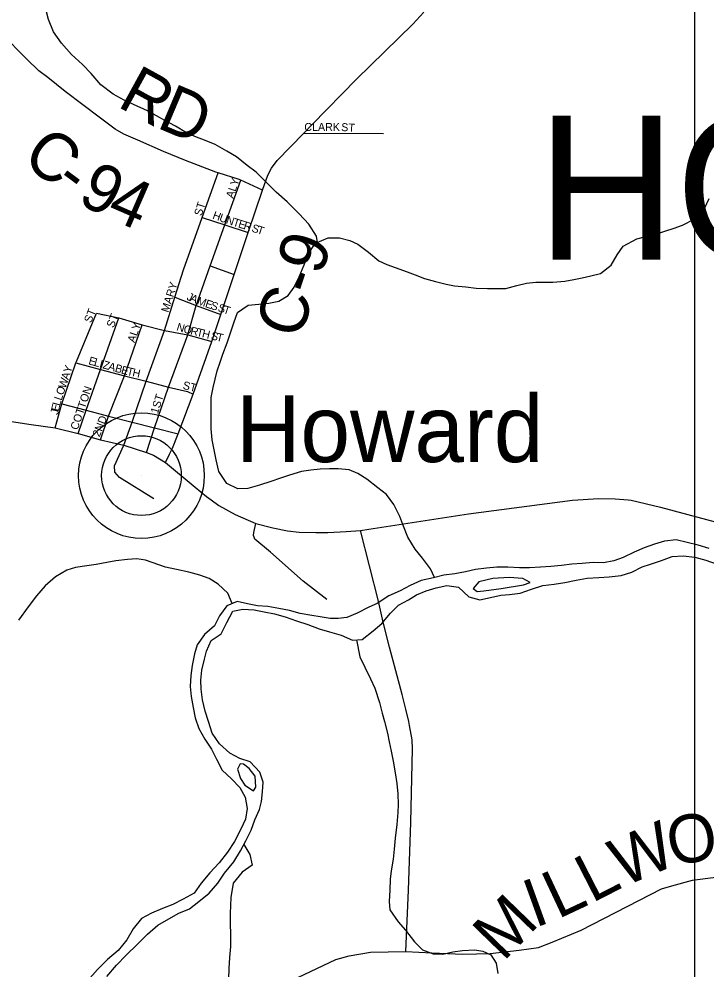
# Model space of a CAD drawing. Extents: x 1759416 to 2214760, y 252598 to 1116833.
# Drawn here: x 2015934 to 2020235, y 873868 to 879811 of the extents above; entities that cross this region are included whole.
import ezdxf

# ---------------------------------------------------------------- set-up
doc = ezdxf.new("R2010")
doc.units = 0
for name, color, linetype in [('GM_X_County_Road', 7, 'Continuous'), ('GM_X_County_Road_Text', 7, 'Continuous'), ('GM_X_Major_River', 7, 'Continuous'), ('GM_X_Minor_River', 7, 'Continuous'), ('GM_X_Township_Road', 7, 'Continuous'), ('GM_X_Township_Road_Text', 7, 'Continuous'), ('GM_X_Township_Subdivision', 7, 'Continuous'), ('GM_X_Township_Subdivision_Text', 7, 'Continuous'), ('GM_X_Township_Text', 7, 'Continuous'), ('GM_X_Unincorporated', 7, 'Continuous'), ('GM_X_Unincorporated_Location', 7, 'Continuous'), ('GM_X_Unincorporated_Text', 7, 'Continuous'), ('GM_X_US_Route', 7, 'Continuous'), ('SC_Scratch1', 7, 'Continuous')]:
    doc.layers.add(name, color=color, linetype=linetype)

msp = doc.modelspace()

# ---------------------------------------------------------------- linework, layer by layer
at = {"layer": 'GM_X_County_Road'}
for points in [[(2017455.9, 878741.5), (2017320.5, 878803), (2017309.8, 878807.8), (2017178.9, 878849.3), (2017163.8, 878854.1), (2016975.8, 878926.4), (2016837.8, 878982.7), (2016677.8, 879053), (2016589.8, 879091.2), (2016535.7, 879123.3), (2016443.8, 879191.5), (2016221.9, 879358.1), (2016113.8, 879444.3), (2016057.9, 879486.5), (2015981.9, 879560.7), (2015822, 879723.2), (2015790, 879749.2), (2015746, 879767.3), (2015682, 879787.4), (2015337.9, 879847.9)], [(2016850.3, 877039.6), (2016875.7, 877090.7), (2016893.9, 877128.1), (2016928.2, 877218.3), (2017023.5, 877467.5), (2017138.9, 877796.5), (2017195.3, 877964.9), (2017278.9, 878214.1), (2017366.8, 878476.1), (2017455.9, 878741.5), (2017490, 878835.6), (2017512, 878879.7), (2017548.1, 878925.7), (2017714, 879097.6), (2017766.4, 879151.9), (2018042.9, 879434), (2018395.4, 879778.2), (2018465.5, 879854.2)], [(2018352, 875498.2), (2018329.2, 875590.8), (2018250.2, 875884.6), (2018211, 876042.6), (2018181, 876173.2), (2018068.8, 876614.5)], [(2018375.5, 875396.2), (2018370.9, 875421.1), (2018352, 875498.2)], [(2018352.4, 873984.9), (2018368.7, 874367.2), (2018384.1, 874790.4), (2018394.3, 875251.1), (2018391.8, 875306.2), (2018375.5, 875396.2)], [(2017636.5, 873803.4), (2017914.7, 873933), (2017997.9, 873956.1), (2018131.8, 873979.2), (2018352.4, 873984.9)]]:
    msp.add_lwpolyline(points, dxfattribs=at)
at = {"layer": 'GM_X_Major_River'}
for points in [[(2020249.7, 876502.6), (2020179.4, 876523.9), (2020111.3, 876539.2), (2020043, 876556.6), (2019969.1, 876547.8), (2019907.2, 876529.1), (2019843.4, 876506.4), (2019779.7, 876479.7), (2019712, 876446.9), (2019652.2, 876424.3), (2019588.3, 876413.6), (2019524.2, 876415), (2019454.2, 876408.2), (2019390.2, 876403.6), (2019326.3, 876396.9), (2019258.3, 876390.2), (2019194.3, 876385.5), (2019126.3, 876380.8), (2019062.3, 876382.2), (2018990.2, 876385.4), (2018922.2, 876384.8), (2018856.2, 876380.1), (2018788.2, 876371.3), (2018724.4, 876356.7), (2018658.5, 876344), (2018590.5, 876335.2), (2018524.6, 876318.5), (2018448.8, 876301.7), (2018379.1, 876270.9), (2018317.3, 876238.3), (2018245.7, 876205.5), (2018174.1, 876158.6), (2018120.3, 876136), (2018048.6, 876097.2), (2017982.9, 876070.5), (2017928.9, 876063.9), (2017878.9, 876065.4), (2017816.7, 876074.8), (2017764.6, 876084.3), (2017692.5, 876095.6), (2017624.2, 876114.9), (2017558.1, 876128.2), (2017489.9, 876139.6), (2017425.8, 876142.9), (2017361.7, 876156.3), (2017297.5, 876171.7), (2017233.7, 876144.9), (2017188.3, 876082.4), (2017156.9, 876019.9), (2017093.5, 875965.2), (2017048.1, 875900.6), (2017030.7, 875844.3), (2017017.4, 875772), (2017008.1, 875707.8), (2017004.8, 875639.7), (2017009.4, 875577.6), (2017022.1, 875507.6), (2017034.8, 875443.6), (2017057.5, 875377.7), (2017096.2, 875310), (2017136.8, 875248.3), (2017169.5, 875186.5), (2017204.2, 875116.7), (2017262.8, 875063.2), (2017315.4, 875007.7), (2017348, 874947.9), (2017360.8, 874877.9), (2017349.4, 874811.6), (2017320.1, 874749.2), (2017280.9, 874670.7), (2017237.5, 874604.1), (2017186.2, 874537.4), (2017126.8, 874474.7), (2017073.4, 874410), (2017028, 874349.4), (2016960.4, 874310.7), (2016894.7, 874277.9), (2016830.9, 874253.2), (2016763.1, 874224.5), (2016699.5, 874189.8), (2016648.1, 874125.1), (2016608.8, 874056.6), (2016553.4, 873989.9), (2016488, 873933.1), (2016424.6, 873872.3), (2016361.2, 873801.6)], [(2016483.1, 873826.9), (2016542.4, 873897.6), (2016603.8, 873960.4), (2016675.1, 874029.2), (2016736.5, 874092), (2016801.9, 874148.8), (2016871.6, 874187.5), (2016933.2, 874224.2), (2016999, 874251), (2017058.6, 874295.7), (2017122.1, 874348.4), (2017177.5, 874411.1), (2017218.8, 874473.7), (2017276.1, 874544.4), (2017319.5, 874612.9), (2017352.8, 874675.4), (2017386.2, 874741.9), (2017407.5, 874806.2), (2017436.9, 874870.6), (2017450.4, 874920.9), (2017455.8, 874981), (2017461.2, 875041.2), (2017440.5, 875105.1), (2017379.8, 875168.6), (2017315.5, 875190), (2017251.2, 875223.4), (2017186.5, 875280.8), (2017141.8, 875348.5), (2017119.1, 875420.4), (2017098.4, 875486.3), (2017081.7, 875556.3), (2017073, 875622.3), (2017070.4, 875678.4), (2017077.7, 875742.6), (2017093, 875810.9), (2017106.5, 875861.1), (2017135.9, 875927.5), (2017197.5, 875968.2), (2017232.8, 876038.8), (2017270.1, 876111.3), (2017334, 876123.9), (2017404.1, 876118.7), (2017466.2, 876107.3), (2017530.4, 876093.9), (2017598.6, 876074.6), (2017668.9, 876049.2), (2017739.2, 876027.9), (2017809.5, 876000.6), (2017875.7, 875981.2), (2017948, 875959.9), (2018018.4, 875928.6), (2018080.3, 875933.2), (2018147.8, 875988), (2018201.4, 876032.7), (2018256.8, 876097.4), (2018306.3, 876148), (2018368, 876180.7), (2018419.7, 876213.3), (2018479.4, 876237.9), (2018541.3, 876256.6), (2018609.2, 876271.3), (2018681.3, 876260), (2018746, 876200.6), (2018814.2, 876181.2), (2018882.1, 876196), (2018946, 876210.7), (2019000, 876215.2), (2019067.9, 876223.9), (2019137.7, 876248.7), (2019209.5, 876271.5), (2019279.5, 876280.2), (2019345.4, 876288.9), (2019417.3, 876303.7), (2019485.2, 876316.4), (2019559.2, 876321.2), (2019623.2, 876325.8), (2019699.1, 876332.6), (2019765, 876353.3), (2019830.7, 876388.1), (2019882.5, 876404.6), (2019950.3, 876427.4), (2020018.1, 876452.1), (2020086.1, 876456.8), (2020158.2, 876447.5), (2020228.4, 876430.2), (2020292.7, 876406.8)], [(2019129.3, 876288.7), (2019083, 876314.3), (2018998.9, 876321.4), (2018896.9, 876314.3), (2018809.1, 876293.4), (2018773.5, 876253)], [(2018773.5, 876253), (2018797.7, 876233.2), (2018839.6, 876237.6), (2018947.6, 876252.8), (2019087.4, 876274.2), (2019129.3, 876288.7)], [(2017315.9, 875155.9), (2017300.2, 875123.7), (2017318.8, 875065.8), (2017345.3, 875024), (2017399.7, 874988.5)], [(2017399.7, 874988.5), (2017415.4, 875010.7), (2017410.7, 875078.8), (2017372.2, 875126.5), (2017337.9, 875154.2), (2017315.9, 875155.9)]]:
    msp.add_lwpolyline(points, dxfattribs=at)
at = {"layer": 'GM_X_Minor_River'}
for points in [[(2017799.6, 878415.1), (2017793.1, 878453.9), (2017746.8, 878527.9), (2017684.5, 878593.8), (2017610.1, 878667.7), (2017541.7, 878729.6), (2017417.1, 878853.4), (2017360.9, 878895.3), (2017292.6, 878949.2), (2017232.3, 878985.1), (2017160.1, 879026.9), (2017093.9, 879052.8), (2017043.8, 879072.7), (2016981.6, 879098.5), (2016911.3, 879140.3), (2016845.1, 879176.2), (2016792.9, 879206.1), (2016736.7, 879235.9), (2016650.4, 879275.7), (2016592.2, 879303.6), (2016522, 879341.4), (2016445.7, 879399.3), (2016385.3, 879469.2), (2016331, 879527.2), (2016262.7, 879589.1), (2016200.3, 879659), (2016150, 879731), (2016117.7, 879807), (2016103.4, 879863.1)], [(2018531.3, 876320.2), (2018506.1, 876374.1), (2018455.7, 876442), (2018411.5, 876498), (2018365.1, 876572), (2018332.8, 876652), (2018314.6, 876702.1), (2018278.2, 876778.1), (2018231.9, 876840.1), (2018177.7, 876882), (2018109.4, 876935.9), (2018053.2, 876969.8), (2017999, 876993.6), (2017928.9, 876999.4), (2017874.8, 876999.2), (2017816.7, 876997), (2017758.7, 876990.8), (2017700.6, 876982.6), (2017624.6, 876960.3), (2017568.6, 876942.1), (2017508.6, 876919.8), (2017436.6, 876897.5), (2017364.6, 876877.3), (2017302.5, 876875), (2017232.3, 876908.9), (2017183.9, 876982.9), (2017165.6, 877057), (2017141.1, 877181.1), (2017134.8, 877249.3), (2017134.4, 877371.5), (2017136.1, 877445.7), (2017147.9, 877507.8), (2017159.7, 877560), (2017173.5, 877612.1), (2017191.3, 877666.3), (2017209.2, 877716.4), (2017234.9, 877786.7), (2017252.8, 877836.8), (2017276.5, 877913.1), (2017300.3, 877977.3), (2017366.2, 878023.6), (2017432.3, 878029.8), (2017496.3, 878034.1), (2017558.4, 878048.3), (2017616.3, 878082.6), (2017654.2, 878134.8), (2017686, 878199), (2017715.7, 878275.3), (2017737.5, 878337.5), (2017787.3, 878409.8), (2017867.3, 878444.1), (2017937.4, 878444.4), (2018001.5, 878426.5), (2018051.7, 878404.7), (2018118, 878352.8), (2018184.3, 878298.9), (2018234.4, 878277), (2018286.6, 878257.2), (2018360.8, 878231.3), (2018410.9, 878211.5), (2018469.1, 878189.6), (2018537.3, 878169.8), (2018605.4, 878154), (2018657.5, 878144.2), (2018727.6, 878136.4), (2018791.8, 878128.6), (2018863.9, 878126.8), (2018978, 878127.2), (2019046, 878145.5), (2019106.1, 878159.7), (2019164.1, 878165.9), (2019214.2, 878166.1), (2019272.3, 878166.3), (2019346.4, 878172.5), (2019402.4, 878182.7), (2019454.4, 878192.9), (2019508.5, 878205.1), (2019568.5, 878221.4), (2019636.4, 878271.7), (2019674.2, 878337.9), (2019712, 878392.2), (2019796, 878436.6), (2019852, 878450.8), (2019914, 878467), (2020030, 878503.5), (2020082, 878521.7), (2020156, 878560), (2020219.8, 878626.4), (2020249.6, 878688.6)], [(2017266.9, 876158.8), (2017238.9, 876223.5), (2017178.6, 876279.4), (2017122.4, 876315.3), (2017064.2, 876335.2), (2016996.1, 876355), (2016917.9, 876370.7), (2016849.7, 876386.5), (2016725.4, 876430.2), (2016671.3, 876438), (2016611.2, 876433.8), (2016539.2, 876425.6), (2016483.1, 876415.4), (2016417.1, 876403.1), (2016357, 876392.9), (2016287, 876382.6), (2016233, 876366.4), (2016163, 876326.1), (2016097.1, 876269.8), (2016043.3, 876205.5), (2015991.5, 876137.2), (2015929.7, 876054.8)], [(2018043.8, 875930.5), (2018065.6, 875825.5), (2018095.8, 875761.4), (2018132.2, 875687.4), (2018158.4, 875629.4), (2018186.8, 875539.3), (2018205.1, 875473.2), (2018219.3, 875421.2), (2018237.6, 875349.1), (2018247.8, 875295), (2018260.1, 875234.9), (2018272.3, 875172.8), (2018284.6, 875100.7), (2018296.9, 875034.7), (2018303.2, 874968.5), (2018303.4, 874902.4), (2018301.6, 874852.3), (2018295.9, 874778.1), (2018286.2, 874691.9), (2018280.4, 874623.8), (2018272.7, 874561.6), (2018260.9, 874487.4), (2018255.1, 874435.3), (2018251.4, 874367.2), (2018247.6, 874297), (2018251.8, 874244.9), (2018304.2, 874168.9), (2018350.5, 874117), (2018406.8, 874045), (2018457.1, 873995.1), (2018523.3, 873969.2), (2018583.4, 873967.4), (2018645.4, 873981.7), (2018707.4, 873989.9), (2018783.5, 873994.2), (2018833.6, 873986.3), (2018883.8, 873962.4), (2018918, 873910.4), (2018928.3, 873846.3)], [(2017340.5, 874652.2), (2017377.3, 874590.7), (2017391.6, 874522.6), (2017329.7, 874480.3), (2017271.9, 874410), (2017258.2, 874321.7), (2017254.6, 874221.5), (2017254.8, 874159.4), (2017257.1, 874089.3), (2017255.4, 874015.1), (2017249.6, 873946.9), (2017245.9, 873876.8), (2017244.1, 873812.7)]]:
    msp.add_lwpolyline(points, dxfattribs=at)
at = {"layer": 'GM_X_Township_Road'}
for points in [[(2017858.6, 876183.6), (2017710.9, 876297.9), (2017506.4, 876479.1), (2017409.1, 876561.1), (2017403.7, 876572), (2017399.3, 876582.9), (2017402.6, 876602.5), (2017414.7, 876658.7)], [(2018352.4, 873984.9), (2018515.2, 873975.7), (2018709.2, 873966.5), (2018878.9, 873971.1), (2019060.8, 873991.9), (2019180.9, 874008), (2019266.3, 874042.7), (2019448.1, 874117.3), (2019808.5, 874303.1), (2019950.7, 874375.1), (2020014.7, 874395), (2020144.8, 874428.9), (2020352.9, 874456.7)]]:
    msp.add_lwpolyline(points, dxfattribs=at)
at = {"layer": 'GM_X_Township_Subdivision'}
for points in [[(2017714, 879097.6), (2018213.6, 879095)], [(2016589.2, 877148.2), (2016641.5, 877291.4), (2016729.7, 877546.7), (2016843.4, 877864.7), (2016907.3, 878071.8), (2016961.6, 878242.4), (2017079.1, 878570.6), (2017178.9, 878849.3)], [(2016731.8, 877102.2), (2016780, 877256.3), (2016868.9, 877509.7), (2016989, 877836.6), (2017041.3, 878020.8), (2017130, 878269.4), (2017220.9, 878524), (2017320.5, 878803)], [(2017079.1, 878570.6), (2017220.9, 878524), (2017366.8, 878476.1)], [(2017130, 878269.4), (2017278.9, 878214.1)], [(2016907.3, 878071.8), (2017041.3, 878020.8), (2017195.3, 877964.9)], [(2016292.6, 877671.3), (2016419.4, 877973.3)], [(2016419.4, 877973.3), (2016558.6, 877943.9), (2016704.2, 877900.5), (2016843.4, 877864.7), (2016989, 877836.6), (2017138.9, 877796.5)], [(2016304.4, 877221), (2016353.8, 877367.1), (2016442.4, 877620.8), (2016558.6, 877943.9)], [(2016443.6, 877181.4), (2016494, 877329.5), (2016594.3, 877581.2), (2016704.2, 877900.5)], [(2016160.1, 877255.5), (2016202.2, 877406.2), (2016289.1, 877662.9), (2016292.6, 877671.3)], [(2016289.1, 877662.9), (2016442.4, 877620.8), (2016594.3, 877581.2), (2016729.7, 877546.7), (2016868.9, 877509.7), (2016986.4, 877482.8), (2017023.5, 877467.5)], [(2016202.2, 877406.2), (2016353.8, 877367.1), (2016494, 877329.5), (2016641.5, 877291.4), (2016780, 877256.3), (2016928.2, 877218.3)], [(2016777.3, 876811.5), (2016562.2, 876946.5), (2016533.9, 876978.7), (2016529.9, 877018.8), (2016589.2, 877148.2)]]:
    msp.add_lwpolyline(points, dxfattribs=at)
at = {"layer": 'GM_X_Unincorporated'}
for radius in [392.8, 249]:
    msp.add_circle((2016699.5, 876957.4), radius, dxfattribs=at)
at = {"layer": 'GM_X_Unincorporated_Location'}
msp.add_line((2016699.5, 876957.4), (2016699.5, 876957.4), dxfattribs=at)
at = {"layer": 'GM_X_US_Route'}
for points in [[(2014125, 877455.4), (2014770.9, 877390.1), (2015426.4, 877341.5), (2015650.2, 877315.5), (2015886.1, 877294.7), (2016009.1, 877277.1)], [(2016009.1, 877277.1), (2016160.1, 877255.5), (2016304.4, 877221), (2016443.6, 877181.4), (2016589.2, 877148.2), (2016731.8, 877102.2), (2016774.7, 877084.5), (2016850.3, 877039.6), (2017034.6, 876884.9), (2017105.6, 876828.1), (2017135.9, 876806.1)], [(2017135.9, 876806.1), (2017183.8, 876771.3), (2017286.1, 876714.7), (2017414.7, 876658.7), (2017521.2, 876630.9), (2017611.8, 876611.9), (2017685.6, 876604.7), (2017789.4, 876601.4), (2017863.8, 876601.4), (2017978.7, 876608), (2018068.8, 876614.5), (2018120.9, 876622.5)], [(2018120.9, 876622.5), (2018745.1, 876718.4), (2019395.1, 876803.7), (2019559.6, 876813.8), (2019661.2, 876811.8), (2019741.7, 876805.2)], [(2019741.7, 876805.2), (2019760.7, 876803.7), (2019943.5, 876761), (2020402.4, 876637.3)]]:
    msp.add_lwpolyline(points, dxfattribs=at)
at = {"layer": 'SC_Scratch1'}
msp.add_lwpolyline([(1984253.2, 880416.3), (2020157.2, 880416.3), (2020157.2, 844512.3), (1984253.2, 844512.3)], close=True, dxfattribs=at)

# ---------------------------------------------------------------- texts
at = {"layer": 'GM_X_County_Road_Text'}
for s, rotation, p in [('R', 331.23692, (2016540.8, 879268)), ('D', 337.06512, (2016786.2, 879135.2)), ('C', 322.34479, (2015942.1, 878922.6)), ('9', 333.62013, (2016290.6, 878664.5)), ('-', 323.38322, (2016141.9, 878768.5)), ('4', 336.43116, (2016470.8, 878575.6)), ('C-9', 71.42001, (2017687.9, 877800.3))]:
    msp.add_text(s, height=300, rotation=rotation, dxfattribs=at).set_placement(p)
at = {"layer": 'GM_X_Township_Road_Text'}
for s, rotation, p in [('W', 22.97081, (2019709.8, 874384.4)), ('O', 10.70983, (2020013.6, 874515.1)), ('L', 27.13719, (2019515.3, 874284.4)), ('L', 25.14742, (2019302, 874184.1)), ('I', 19.86439, (2019158.2, 874130.7)), ('M', 45.94822, (2018961.8, 873916.1))]:
    msp.add_text(s, height=300, rotation=rotation, dxfattribs=at).set_placement(p)
at = {"layer": 'GM_X_Township_Subdivision_Text'}
for s, rotation, p in [('CLARK', 0.00001, (2017717.5, 879111)), ('ST', 356.42537, (2017946.9, 879111)), ('ALY', 71.56019, (2017273, 878686.6)), ('ST', 72.6413, (2017074.9, 878576.4)), ('H', 339.80213, (2017140, 878564.9)), ('U', 340.19713, (2017181.6, 878549.6)), ('N', 342.10582, (2017224.7, 878534.1)), ('T', 342.50842, (2017267, 878520.4)), ('E', 342.52472, (2017300.6, 878509.9)), ('R', 342.52913, (2017334.1, 878499.3)), ('S', 342.52472, (2017384.5, 878483.4)), ('T', 342.52472, (2017418.1, 878472.9)), ('MARY', 72.40604, (2016868, 877973.4)), ('J', 335.13631, (2016977.9, 878058.6)), ('A', 335.8295, (2016998.5, 878049)), ('M', 340.76369, (2017043, 878029.3)), ('E', 341.96925, (2017093.9, 878011.5)), ('S', 341.94518, (2017127.4, 878000.6)), ('S', 341.95287, (2017173.4, 877985.6)), ('T', 341.91921, (2017206.9, 877974.7)), ('ST', 68.19607, (2016384.4, 877908.3)), ('ST', 68.19607, (2016525.2, 877877.5)), ('ALY', 71.56747, (2016657.1, 877784.6)), ('N', 343.67336, (2016915, 877865.5)), ('O', 344.51716, (2016958, 877852.9)), ('R', 346.31545, (2017002, 877840.7)), ('T', 346.49277, (2017040.6, 877831.3)), ('H', 346.49171, (2017074.9, 877823.1)), ('S', 346.50856, (2017130.5, 877809.7)), ('T', 346.50856, (2017164.8, 877801.5)), ('E', 344.20096, (2016364.9, 877654.3)), ('L', 344.21234, (2016398.7, 877644.7)), ('I', 344.19272, (2016432.6, 877635.1)), ('Z', 344.21234, (2016453.8, 877629.2)), ('A', 344.19272, (2016487.6, 877619.6)), ('Y', 71.56504, (2016256.3, 877594.6)), ('B', 344.20362, (2016530, 877607.6)), ('E', 345.18655, (2016569, 877596.6)), ('T', 347.26866, (2016605, 877587.1)), ('H', 347.71923, (2016639.7, 877579.3)), ('W', 71.55973, (2016224.3, 877498.6)), ('A', 71.56504, (2016242.4, 877552.8)), ('ST', 345.96055, (2016954.2, 877500.4)), ('O', 71.56504, (2016210.4, 877456.8)), ('COTTON', 71.2403, (2016300.6, 877239.1)), ('L', 74.42615, (2016190.2, 877390.1)), ('L', 71.91071, (2016199.5, 877423.5)), ('1ST', 72.34946, (2016802.1, 877340.1)), ('J', 76.67434, (2016177.1, 877335)), ('E', 76.65307, (2016182.2, 877356.4)), ('2ND', 68.20009, (2016437.3, 877195.5))]:
    msp.add_text(s, height=50, rotation=rotation, dxfattribs=at).set_placement(p)
at = {"layer": 'GM_X_Township_Text'}
msp.add_text('HOWARD', height=900, rotation=0.00001, dxfattribs=at).set_placement((2019171.8, 878307.1))
at = {"layer": 'GM_X_Unincorporated_Text'}
msp.add_text('Howard', height=417, rotation=0.00001, dxfattribs=at).set_placement((2017290.7, 877042.2))

doc.saveas('drawing.dxf')
